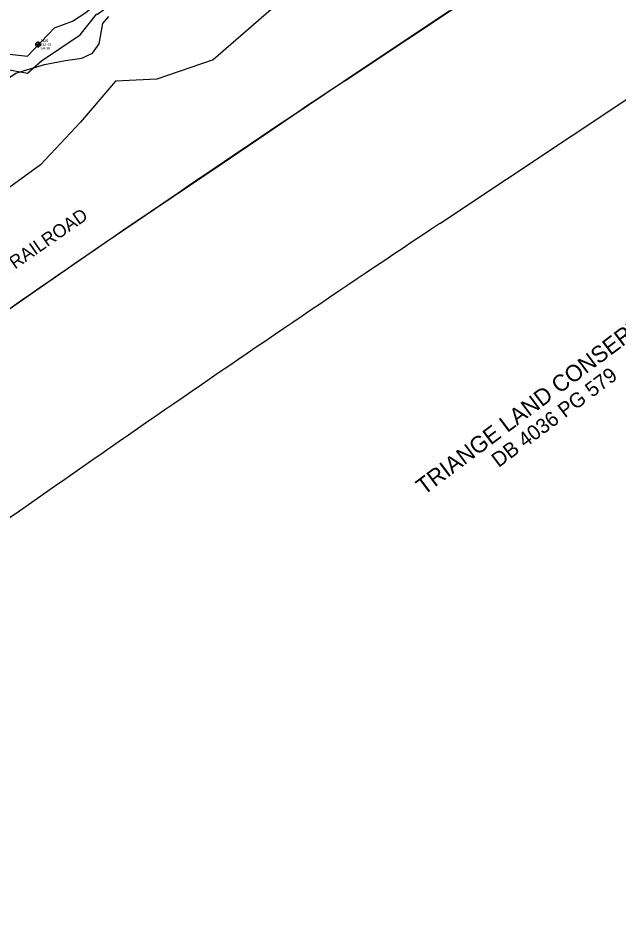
# Model space of a CAD drawing. Extents: x 2186615 to 2188822, y 629899 to 631820.
# Drawn here: x 2187466.7 to 2187648.6, y 630299.1 to 630571.8 of the extents above; entities that cross this region are included whole.
import ezdxf

# ---------------------------------------------------------------- set-up
doc = ezdxf.new("R2010")
doc.units = 0
for name, color, linetype in [('Exist Environmental Wetland Boundary Cogo Comment', 7, 'Continuous'), ('Exist Environmental Wetland Boundary Cogo Elevation', 7, 'Continuous'), ('Exist Environmental Wetland Boundary Cogo Number', 7, 'Continuous'), ('Exist Environmental Wetland Boundary Cogo Point CELL', 7, 'Continuous'), ('Exist Hydro Jurisdictional Stream or Body of Water', 7, 'Continuous'), ('Exist Property Deed Book Text', 7, 'Continuous'), ('Exist Property Owner Text', 7, 'Continuous'), ('Exist Railroads Standard Gauge', 7, 'Continuous'), ('Exist Railroads Standard Gauge Text', 7, 'Continuous'), ('Exist Right of Way Line', 7, 'Continuous'), ('Exist Vegetation Woods Line', 7, 'Continuous'), ('Scratch_Level_1', 7, 'Continuous')]:
    doc.layers.add(name, color=color, linetype=linetype)

msp = doc.modelspace()

# ---------------------------------------------------------------- linework, layer by layer
at = {"layer": 'Exist Environmental Wetland Boundary Cogo Point CELL'}
msp.add_lwpolyline([(2187472.79, 630564.71), (2187472.79, 630562.91), (2187472.79, 630563.81), (2187473.69, 630563.81), (2187471.89, 630563.81)], dxfattribs=at)
msp.add_circle((2187472.79, 630563.81), 0.703, dxfattribs=at)
at = {"layer": 'Exist Hydro Jurisdictional Stream or Body of Water'}
for points in [[(2187449.56, 630557.04), (2187457.67, 630561.55), (2187469.6, 630560.19), (2187477.83, 630568.81), (2187483.29, 630570.83), (2187487.27, 630573.49), (2187494.84, 630580), (2187501.28, 630583.62), (2187529.01, 630602.42), (2187543.47, 630612.86), (2187569.07, 630628.39), (2187588.84, 630647.49), (2187600.3, 630658.9), (2187631.69, 630675.75), (2187643.77, 630689.68), (2187651.01, 630689.99), (2187663.15, 630692.5)], [(2187447.83, 630554.37), (2187455.66, 630557.6), (2187469.6, 630555.05), (2187473.86, 630558.86), (2187485.6, 630566.69), (2187490.63, 630573.04), (2187490.78, 630573.03), (2187503.45, 630582.34), (2187528.93, 630598.21), (2187547.35, 630610.71), (2187554.69, 630615.02), (2187566.17, 630622.44), (2187570.59, 630621.55), (2187578.03, 630632.5), (2187587.26, 630641.63), (2187602.46, 630652.89), (2187618.95, 630664.76), (2187633.75, 630672.36)]]:
    msp.add_lwpolyline(points, dxfattribs=at)
at = {"layer": 'Exist Railroads Standard Gauge'}
msp.add_lwpolyline([(2187610.96, 630583.01), (2187591.05, 630569.62), (2187570.73, 630556.06), (2187549.48, 630541.74), (2187528.61, 630527.61), (2187508.22, 630513.81), (2187490.96, 630502.05), (2187472.11, 630489.07), (2187449.98, 630473.71)], dxfattribs=at)
at = {"layer": 'Exist Right of Way Line'}
msp.add_line((2187594.65, 630509.49), (2187922.56, 630728.12), dxfattribs=at)
for radius in [6398.3, 6268.3]:
    msp.add_arc((2191071.84, 625294.06), radius, 123.691884, 125.65722, dxfattribs=at)
at = {"layer": 'Exist Vegetation Woods Line'}
for points in [[(2187105.73, 630299.09), (2187150.8, 630331.83), (2187206.11, 630372.03), (2187256.07, 630407.26), (2187300.91, 630439.29), (2187349.47, 630473.88), (2187396.87, 630507.87), (2187440.69, 630538.21), (2187466.07, 630555.07), (2187474.72, 630557.75), (2187481.17, 630558.92), (2187486.05, 630559.68), (2187489.3, 630561.14), (2187491.38, 630563.95), (2187492.45, 630570.17), (2187494.25, 630572.31)], [(2187543.45, 630574.43), (2187525.86, 630559.12), (2187508.81, 630553.24), (2187496.25, 630552.62), (2187485.65, 630540.19), (2187473.57, 630527.3), (2187453.75, 630512.92)]]:
    msp.add_lwpolyline(points, dxfattribs=at)
at = {"layer": 'Scratch_Level_1'}
msp.add_line((2187565.8, 630552.76), (2187893.71, 630771.38), dxfattribs=at)
msp.add_arc((2191071.84, 625294.06), 6320.3, 123.691884, 125.65722, dxfattribs=at)

# ---------------------------------------------------------------- texts
at = {"layer": 'Exist Environmental Wetland Boundary Cogo Comment'}
msp.add_text('SA-38', height=0.75, dxfattribs=at).set_placement((2187473.54, 630562.31))
at = {"layer": 'Exist Environmental Wetland Boundary Cogo Elevation'}
msp.add_text('112.43', height=0.75, dxfattribs=at).set_placement((2187473.54, 630563.43))
at = {"layer": 'Exist Environmental Wetland Boundary Cogo Number'}
msp.add_text('1438', height=0.75, dxfattribs=at).set_placement((2187473.54, 630564.56))
at = {"layer": 'Exist Property Deed Book Text'}
msp.add_text('DB 4036 PG 579', height=4.5, rotation=36.8593, dxfattribs=at).set_placement((2187612.44, 630435.28))
at = {"layer": 'Exist Property Owner Text'}
msp.add_text('TRIANGE LAND CONSERVANCY', height=5, rotation=36.8593, dxfattribs=at).set_placement((2187589.82, 630426.92))
at = {"layer": 'Exist Railroads Standard Gauge Text'}
msp.add_text('SEABOARD COASTLINE RAILROAD', height=4, rotation=34.7727, dxfattribs=at).set_placement((2187414.05, 630459.54))

doc.saveas('drawing.dxf')
